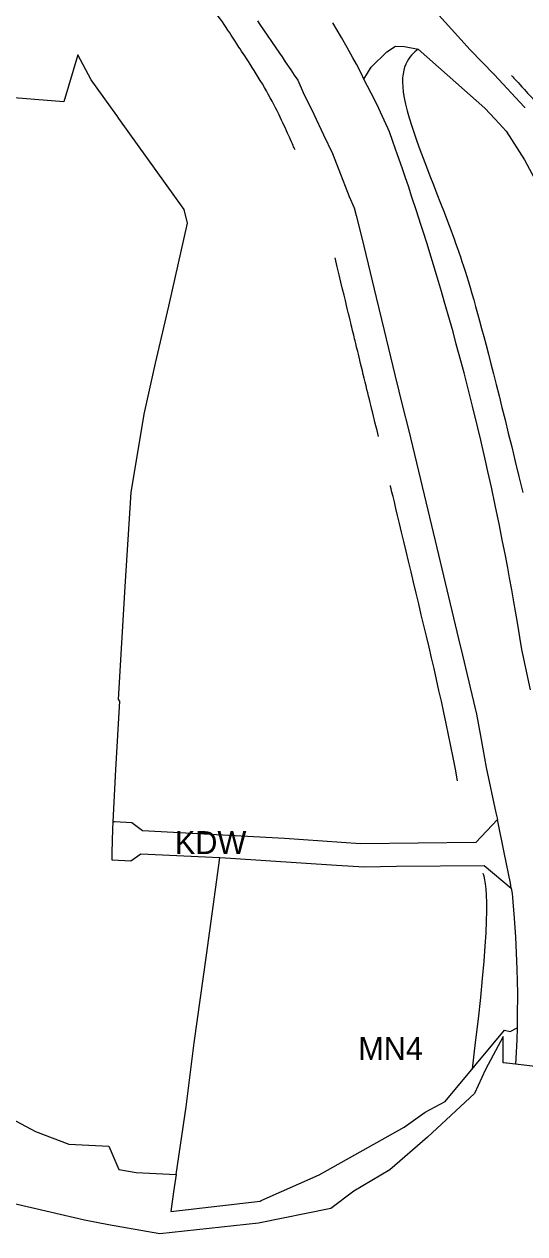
# Model space of a CAD drawing. Extents: x 7413438 to 7416393, y 5541665 to 5544118.
# Drawn here: x 7414942.1 to 7415073.3, y 5541700 to 5542017 of the extents above; entities that cross this region are included whole.
import ezdxf

# ---------------------------------------------------------------- set-up
doc = ezdxf.new("R2010")
doc.units = 0
for name, color, linetype in [('linie_rozgraniczajace', 7, 'Continuous'), ('linie_zabudowy_nieprzekraczalne', 7, 'Continuous'), ('oznaczenia_przeznaczen', 7, 'Continuous')]:
    doc.layers.add(name, color=color, linetype=linetype)

msp = doc.modelspace()

# ---------------------------------------------------------------- linework, layer by layer
at = {"layer": 'linie_rozgraniczajace'}
for p, q in [((7415059, 5542010.24), (7415047.56, 5542022.91)), ((7415003.24, 5542017.85), (7415003.89, 5542016.89)), ((7415003.89, 5542016.89), (7415008.99, 5542009.37)), ((7415025.24, 5542013.45), (7415022.97, 5542017.28)), ((7415026.72, 5542010.87), (7415025.24, 5542013.45)), ((7415028.22, 5542008.18), (7415026.72, 5542010.87)), ((7415037.16, 5542009.68), (7415039.43, 5542011.21)), ((7415039.43, 5542011.21), (7415041.77, 5542011.09)), ((7415041.77, 5542011.09), (7415045.35, 5542010.43)), ((7415045.35, 5542010.43), (7415062.82, 5541994.99)), ((7415065.28, 5542003.81), (7415059, 5542010.24)), ((7414956.11, 5542008.93), (7414952.51, 5541996.58)), ((7414959.62, 5542002.42), (7414956.11, 5542008.93)), ((7415008.99, 5542009.37), (7415009.68, 5542008.36)), ((7415009.68, 5542008.36), (7415010.52, 5542007.13)), ((7415010.52, 5542007.13), (7415011.97, 5542004.98)), ((7415029.16, 5542006.44), (7415028.22, 5542008.18)), ((7415033.05, 5542005.72), (7415037.16, 5542009.68)), ((7414952.51, 5541996.58), (7414840.1, 5542005.99)), ((7415011.97, 5542004.98), (7415012.89, 5542003.63)), ((7415012.89, 5542003.63), (7415013.81, 5542002.28)), ((7415030.48, 5542003.97), (7415029.16, 5542006.44)), ((7415031.09, 5542002.55), (7415030.48, 5542003.97)), ((7415031.1, 5542002.56), (7415033.05, 5542005.72)), ((7415065.33, 5542003.76), (7415065.28, 5542003.81)), ((7415065.39, 5542003.71), (7415065.33, 5542003.76)), ((7415073.14, 5541995.28), (7415065.39, 5542003.71)), ((7414966.34, 5541993.04), (7414959.62, 5542002.42)), ((7415013.81, 5542002.28), (7415015.25, 5541999.02)), ((7415031.11, 5542002.54), (7415031.09, 5542002.55)), ((7415031.11, 5542002.54), (7415031.1, 5542002.56)), ((7415033.07, 5541998.9), (7415031.11, 5542002.54)), ((7415015.25, 5541999.02), (7415018.02, 5541993.35)), ((7415034.14, 5541996.71), (7415033.07, 5541998.9)), ((7415035.02, 5541994.89), (7415034.14, 5541996.71)), ((7415035.95, 5541992.91), (7415035.02, 5541994.89)), ((7415062.82, 5541994.99), (7415065.51, 5541992.07)), ((7415073.31, 5541995.1), (7415073.14, 5541995.28)), ((7415073.32, 5541995.08), (7415073.31, 5541995.1)), ((7414966.42, 5541992.93), (7414966.34, 5541993.04)), ((7414966.93, 5541992.22), (7414966.42, 5541992.93)), ((7414984.01, 5541968.38), (7414966.93, 5541992.22)), ((7415018.02, 5541993.35), (7415020.55, 5541987.99)), ((7415037.47, 5541989.58), (7415035.95, 5541992.91)), ((7415065.51, 5541992.07), (7415068.42, 5541988.9)), ((7415020.55, 5541987.99), (7415022.86, 5541983.09)), ((7415037.8, 5541988.79), (7415037.47, 5541989.58)), ((7415038.73, 5541986.18), (7415037.8, 5541988.79)), ((7415068.42, 5541988.9), (7415073.24, 5541981.44)), ((7415039.94, 5541982.74), (7415038.73, 5541986.18)), ((7415022.86, 5541983.09), (7415024.59, 5541978.81)), ((7415041.12, 5541979.34), (7415039.94, 5541982.74)), ((7415073.24, 5541981.44), (7415087.5, 5541954.65)), ((7415024.59, 5541978.81), (7415027.31, 5541971.79)), ((7415042.02, 5541976.71), (7415041.12, 5541979.34)), ((7415042.78, 5541974.49), (7415042.02, 5541976.71)), ((7415027.31, 5541971.79), (7415028.62, 5541968.83)), ((7415043.72, 5541971.66), (7415042.78, 5541974.49)), ((7415028.62, 5541968.83), (7415029.12, 5541966.82)), ((7415044.9, 5541968.08), (7415043.72, 5541971.66)), ((7414984.88, 5541964.79), (7414984.01, 5541968.38)), ((7415029.12, 5541966.82), (7415030.55, 5541961.02)), ((7415046.06, 5541964.5), (7415044.9, 5541968.08)), ((7414979.96, 5541943.1), (7414984.88, 5541964.79)), ((7415046.64, 5541962.67), (7415046.06, 5541964.5)), ((7415047.68, 5541959.38), (7415046.64, 5541962.67)), ((7415030.55, 5541961.02), (7415033.29, 5541949.71)), ((7415048.13, 5541957.94), (7415047.68, 5541959.38)), ((7415049.03, 5541955.02), (7415048.13, 5541957.94)), ((7415050.16, 5541951.29), (7415049.03, 5541955.02)), ((7415033.29, 5541949.71), (7415034.34, 5541945.37)), ((7415051.46, 5541946.93), (7415050.16, 5541951.29)), ((7415052.2, 5541944.4), (7415051.46, 5541946.93)), ((7415034.34, 5541945.37), (7415036.44, 5541936.66)), ((7415053.65, 5541939.31), (7415052.2, 5541944.4)), ((7414976.54, 5541928.12), (7414979.96, 5541943.1)), ((7415054.52, 5541936.35), (7415053.65, 5541939.31)), ((7415036.44, 5541936.66), (7415039.28, 5541925.07)), ((7415055.36, 5541933.14), (7415054.52, 5541936.35)), ((7415056.54, 5541928.76), (7415055.36, 5541933.14)), ((7414973.5, 5541914.79), (7414976.54, 5541928.12)), ((7415057.38, 5541925.6), (7415056.54, 5541928.76)), ((7415039.28, 5541925.07), (7415041.37, 5541916.52)), ((7415058.47, 5541921.39), (7415057.38, 5541925.6)), ((7415059.61, 5541916.84), (7415058.47, 5541921.39)), ((7414970.15, 5541894.26), (7414973.5, 5541914.79)), ((7415041.37, 5541916.52), (7415042.78, 5541910.78)), ((7415060.98, 5541911.24), (7415059.61, 5541916.84)), ((7415042.78, 5541910.78), (7415045.98, 5541897.67)), ((7415061.77, 5541907.95), (7415060.98, 5541911.24)), ((7415062.13, 5541906.41), (7415061.77, 5541907.95)), ((7415062.92, 5541902.96), (7415062.13, 5541906.41)), ((7415063.64, 5541899.79), (7415062.92, 5541902.96)), ((7415064.55, 5541895.64), (7415063.64, 5541899.79)), ((7415045.98, 5541897.67), (7415047.38, 5541891.83)), ((7414968.57, 5541869.64), (7414970.15, 5541894.26)), ((7415065.55, 5541890.98), (7415064.55, 5541895.64)), ((7415047.38, 5541891.83), (7415049.83, 5541881.59)), ((7415066.67, 5541885.59), (7415065.55, 5541890.98)), ((7415067.41, 5541881.88), (7415066.67, 5541885.59)), ((7415049.83, 5541881.59), (7415055.97, 5541855.88)), ((7415068.22, 5541877.71), (7415067.41, 5541881.88)), ((7415068.82, 5541874.56), (7415068.22, 5541877.71)), ((7415069.31, 5541871.91), (7415068.82, 5541874.56)), ((7415069.89, 5541868.72), (7415069.31, 5541871.91)), ((7414966.81, 5541840.04), (7414968.57, 5541869.64)), ((7415070.44, 5541865.64), (7415069.89, 5541868.72)), ((7415070.87, 5541863.12), (7415070.44, 5541865.64)), ((7415071.45, 5541859.68), (7415070.87, 5541863.12)), ((7415072, 5541856.36), (7415071.45, 5541859.68)), ((7415055.97, 5541855.88), (7415056.98, 5541851.65)), ((7415072.52, 5541853.1), (7415072, 5541856.36)), ((7415056.98, 5541851.65), (7415060.64, 5541836.2)), ((7415074.83, 5541842.59), (7415072.52, 5541853.1)), ((7414966.15, 5541821.66), (7414967.16, 5541839.61)), ((7414967.16, 5541839.61), (7414966.81, 5541840.04)), ((7415060.64, 5541836.2), (7415061.68, 5541830.54)), ((7415061.68, 5541830.54), (7415062.33, 5541827.05)), ((7415062.33, 5541827.05), (7415063.22, 5541822.23)), ((7414965.41, 5541807.97), (7414966.15, 5541821.66)), ((7415063.22, 5541822.23), (7415065.74, 5541810.36)), ((7415065.74, 5541810.36), (7415066.11, 5541808.55)), ((7414965.29, 5541807.97), (7414965.24, 5541806.01)), ((7414965.41, 5541807.97), (7414965.29, 5541807.97)), ((7414965.62, 5541807.97), (7414965.41, 5541807.97)), ((7414965.74, 5541807.97), (7414965.62, 5541807.97)), ((7414970.29, 5541807.74), (7414965.74, 5541807.97)), ((7414973.08, 5541805.57), (7414970.29, 5541807.74)), ((7415066.11, 5541808.55), (7415060.43, 5541802.59)), ((7415067.89, 5541799.91), (7415066.11, 5541808.55)), ((7414965.24, 5541806.01), (7414965.07, 5541799.96)), ((7415010.31, 5541803.57), (7414973.08, 5541805.57)), ((7415030.28, 5541802.21), (7415010.31, 5541803.57)), ((7415060.43, 5541802.59), (7415030.28, 5541802.21)), ((7414965.07, 5541799.96), (7414965.02, 5541798)), ((7414965.02, 5541798), (7414965.04, 5541797.99)), ((7414965.04, 5541797.99), (7414965.25, 5541797.98)), ((7414965.25, 5541797.98), (7414970.01, 5541797.74)), ((7414970.01, 5541797.74), (7414972.68, 5541799.61)), ((7414972.68, 5541799.61), (7414993.39, 5541798.58)), ((7414993.12, 5541796.59), (7414993.39, 5541798.58)), ((7414993.39, 5541798.58), (7414996.14, 5541798.44)), ((7414996.14, 5541798.44), (7415023.94, 5541796.63)), ((7415069.6, 5541791.9), (7415067.89, 5541799.91)), ((7414989.91, 5541773), (7414993.12, 5541796.59)), ((7414993.12, 5541796.59), (7414993.12, 5541796.59)), ((7415023.94, 5541796.63), (7415031.25, 5541796.21)), ((7415031.25, 5541796.21), (7415039.72, 5541796.32)), ((7415039.72, 5541796.32), (7415062.62, 5541796.51)), ((7415062.62, 5541796.51), (7415069.77, 5541790.63)), ((7415069.77, 5541790.63), (7415069.6, 5541791.9)), ((7415069.77, 5541790.63), (7415069.96, 5541789.23)), ((7415069.96, 5541789.23), (7415070.06, 5541788.15)), ((7415070.06, 5541788.15), (7415070.27, 5541785.85)), ((7415070.27, 5541785.85), (7415070.44, 5541783.83)), ((7415070.44, 5541783.83), (7415070.86, 5541777.85)), ((7415070.86, 5541777.85), (7415071.24, 5541769.37)), ((7414986.67, 5541750.06), (7414989.91, 5541773)), ((7415071.24, 5541769.37), (7415071.35, 5541763.07)), ((7415071.35, 5541763.07), (7415071.34, 5541756.94)), ((7415071.34, 5541756.94), (7415071.28, 5541754.03)), ((7415052.44, 5541734.73), (7415067.98, 5541753.34)), ((7415067.98, 5541753.34), (7415069.45, 5541753.07)), ((7415069.45, 5541753.07), (7415071.28, 5541754.03)), ((7415071.28, 5541754.03), (7415071.19, 5541750.85)), ((7414984.53, 5541733.3), (7414986.67, 5541750.06)), ((7415067.63, 5541751.72), (7415063.04, 5541743.07)), ((7415067.68, 5541744.84), (7415067.63, 5541751.72)), ((7415071.19, 5541750.85), (7415070.98, 5541745.95)), ((7415068.47, 5541744.75), (7415067.68, 5541744.84)), ((7415068.6, 5541744.73), (7415068.47, 5541744.75)), ((7415070.89, 5541744.46), (7415068.6, 5541744.73)), ((7415070.98, 5541745.95), (7415070.89, 5541744.46)), ((7415087.36, 5541742.49), (7415070.89, 5541744.46)), ((7415063.04, 5541743.07), (7415060.11, 5541736.81)), ((7415047.17, 5541731.93), (7415052.44, 5541734.73)), ((7415060.11, 5541736.81), (7415047.79, 5541725.32)), ((7414981.92, 5541715.58), (7414984.53, 5541733.3)), ((7415041.69, 5541727.93), (7415047.17, 5541731.93)), ((7414937.57, 5541730.82), (7414945.05, 5541726.8)), ((7415019.43, 5541715.44), (7415041.69, 5541727.93)), ((7414945.05, 5541726.8), (7414953.78, 5541723.51)), ((7415047.79, 5541725.32), (7415037.9, 5541716.8)), ((7414953.78, 5541723.51), (7414964.31, 5541722.98)), ((7414964.31, 5541722.98), (7414966.87, 5541716.91)), ((7414966.87, 5541716.91), (7414971.47, 5541716.05)), ((7414971.47, 5541716.05), (7414981.92, 5541715.58)), ((7414981.92, 5541715.58), (7414981.26, 5541711.02)), ((7415004.24, 5541708.74), (7415019.43, 5541715.44)), ((7415037.9, 5541716.8), (7415028.48, 5541711.17)), ((7414981.26, 5541711.02), (7414980.49, 5541705.83)), ((7415003.95, 5541708.61), (7415004.24, 5541708.74)), ((7415028.48, 5541711.17), (7415022.42, 5541706.67)), ((7414948.93, 5541705.71), (7414939.11, 5541707.99)), ((7414957.93, 5541703.62), (7414948.93, 5541705.71)), ((7414980.49, 5541705.83), (7415003.95, 5541708.61)), ((7415022.42, 5541706.67), (7415003.51, 5541702.78)), ((7414964.17, 5541702.42), (7414957.93, 5541703.62)), ((7414977.64, 5541700.03), (7414964.17, 5541702.42)), ((7415003.51, 5541702.78), (7414977.64, 5541700.03))]:
    msp.add_line(p, q, dxfattribs=at)
at = {"layer": 'linie_zabudowy_nieprzekraczalne'}
for points in [[(7415013.08, 5541984.02), (7415012.81, 5541984.63), (7415012.81, 5541984.63), (7415006.73, 5541998.37), (7414996.72, 5542013.5), (7414996.71, 5542013.5), (7414989.22, 5542024.83), (7414976.1, 5542040.43)], [(7415045.32, 5542010.38), (7415043.14, 5542008.65), (7415037.14, 5542003.31), (7415055.38, 5541961.4), (7415061.69, 5541940.03), (7415072.8, 5541894.22)], [(7415069.83, 5542003.5), (7415070.86, 5542002.39), (7415070.87, 5542002.38), (7415080.88, 5541991.49), (7415081.07, 5541991.27), (7415081.31, 5541990.96), (7415081.53, 5541990.64), (7415081.53, 5541990.63), (7415086.92, 5541982.1), (7415094.11, 5541972.46), (7415094.15, 5541972.4), (7415094.18, 5541972.35), (7415102.18, 5541961.13), (7415102.34, 5541960.9), (7415105.24, 5541956.4), (7415115.78, 5541940.12)], [(7415034.95, 5541908.95), (7415033.79, 5541913.67), (7415033.79, 5541913.68), (7415028.65, 5541934.7), (7415028.64, 5541934.72), (7415026.7, 5541942.75), (7415023.56, 5541955.74)], [(7415055.7, 5541818.69), (7415052.64, 5541835.25), (7415045.61, 5541864.63), (7415038.17, 5541895.74), (7415038.09, 5541896.05)], [(7415059.57, 5541743.24), (7415064.47, 5541781.67), (7415063.59, 5541790.85), (7415062.4, 5541794.45)]]:
    msp.add_open_spline(points, degree=3, dxfattribs=at)

# ---------------------------------------------------------------- texts
at = {"layer": 'oznaczenia_przeznaczen'}
for s, p in [('KDW', (7414981.59, 5541799.53)), ('MN4', (7415029.65, 5541745.58))]:
    msp.add_text(s, height=6, dxfattribs=at).set_placement(p)

doc.saveas('drawing.dxf')
